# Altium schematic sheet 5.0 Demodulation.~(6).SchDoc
size A4; SheetNumber: 5; SheetTotal: 6
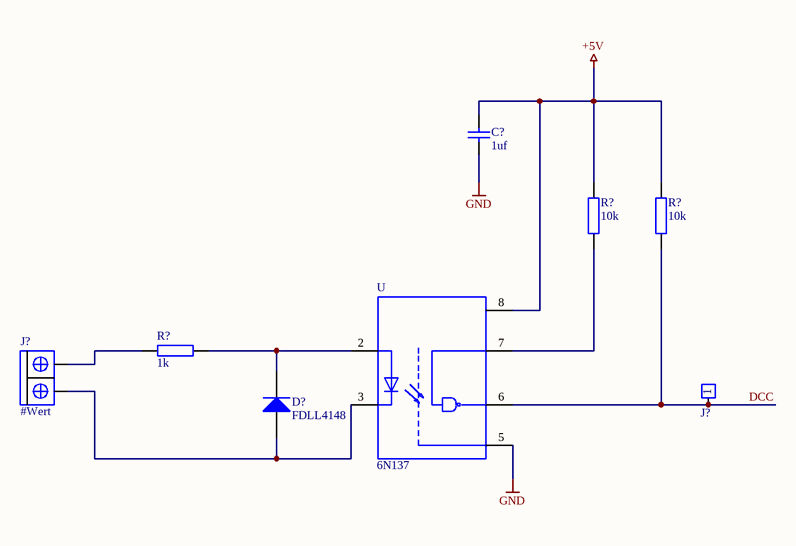
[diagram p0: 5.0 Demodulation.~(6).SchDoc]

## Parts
(Parts that share a designator on the sheet are numbered #1, #2 ... from top to bottom, then left to right.)
C?  1uf  [C_SMD_0805]
D?  FDLL4148  [D_SMD_1206]
J?#1  #Wert  [J_THT_Printklemme 2x]
J?#2  #Wert  [SIP-1]  (value not drawn)
R?#1  10k  [R_SMD_0805]
R?#2  10k  [R_SMD_0805]
R?#3  1k  [R_SMD_0805]
U  6N137  [DIP762W50P254L977H451Q8]

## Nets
+5V: C?.1 R?#1.2 R?#2.2 U.8(VCC)
GND: C?.2 U.5(GND)
DCC: J?#2.1 R?#2.1 U.6(VO)
NetD?_1: D?.1(A) J?#1.1 U.3(C)
NetD?_2: D?.2(K) R?#3.2 U.2(A)
NetJ?#1_2: J?#1.2 R?#3.1
NetR?#1_1: R?#1.1 U.7(VE)

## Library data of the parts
C? = C_SMD_KO: Kondensator SMD Universal, Keramik, Folie, usw.
D? = D_SMD_Silizium: Diode SMD Silizium; Spannung For.: 0,7V
J?#1 = J_THT_Printklemme 2x: Printklemme
J?#2 = J_THT_CON1: Stecker
R?#1-R?#3 = R_SMD_Widerstand: Widerstand SMD
U = 6N137: Optoaislador de salida lÃ³gica 10Mbps Open Collector 5000Vrms 1 Channel 5kV / Âµs CMTI 8-DIP; MF: Everlight Electronics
